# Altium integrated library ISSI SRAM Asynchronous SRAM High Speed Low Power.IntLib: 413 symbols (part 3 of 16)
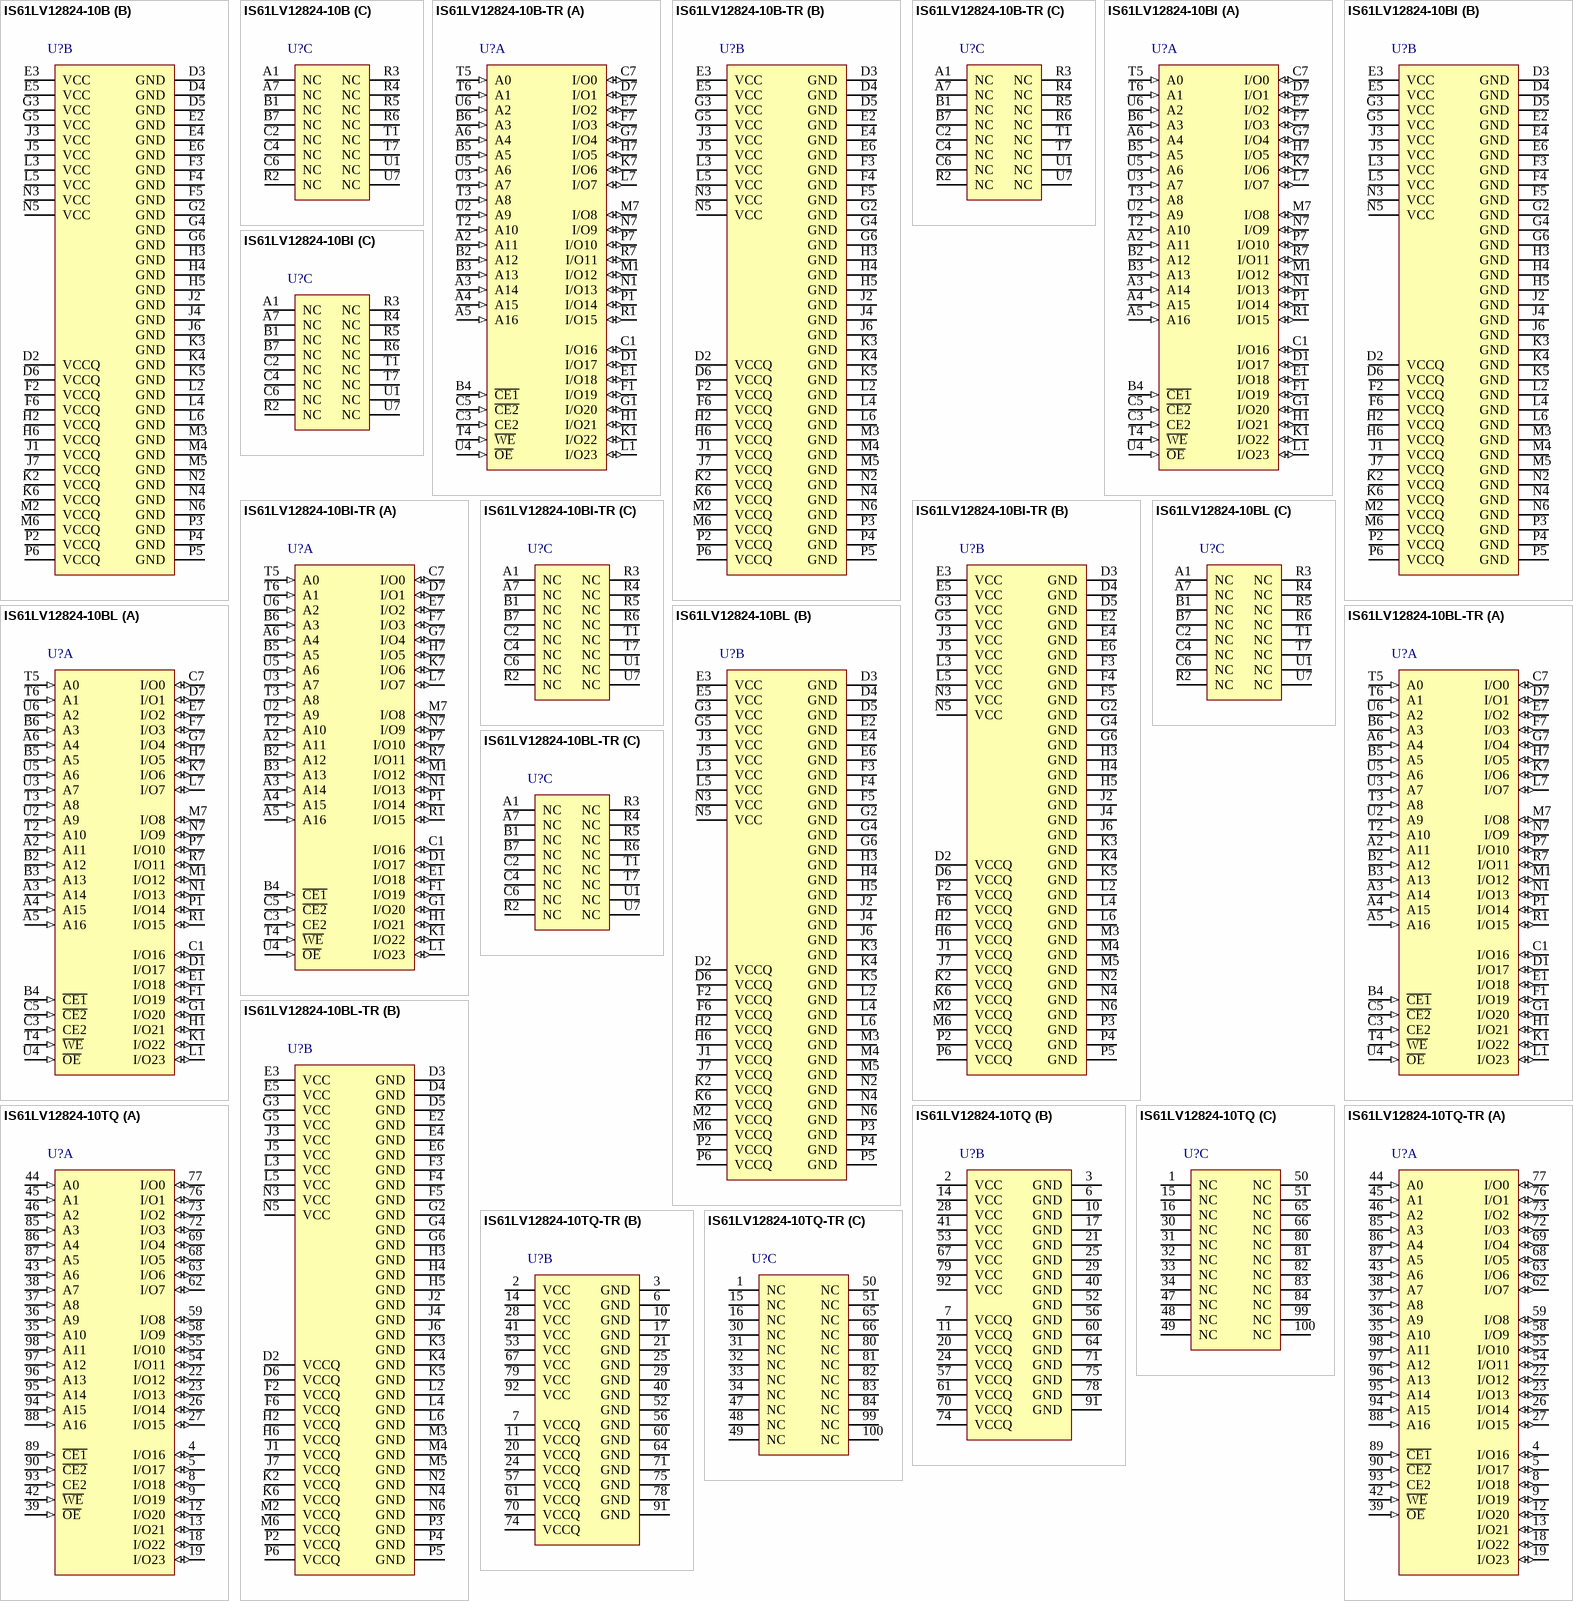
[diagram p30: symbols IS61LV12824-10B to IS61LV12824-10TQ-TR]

## IS61LV12824-10TQ-TR
designator U?
3 M High Speed CMOS SRAM with 3.3 V Supply, 128 K x 24, 0 to 70 degC, 100-Pin QFP (TQFP-100); Manufacturer: Integrated Silicon Solution Inc (ISSI); PartNumber: IS61LV12824-10TQ-TR; Density: 3M; Packing: Tape & Reel; Speed (ns): 10
footprint ISSI-TQFP-100-20000X14000DE_N (QFP, 100-Leads, Body 20x14mm, Pitch 0.65mm, IPC Medium Density)
part A pins: 4 I/O16 (io) "Data Input/Output", 5 I/O17 (io) "Data Input/Output", 8 I/O18 (io) "Data Input/Output", 9 I/O19 (io) "Data Input/Output", 12 I/O20 (io) "Data Input/Output", 13 I/O21 (io) "Data Input/Output", 18 I/O22 (io) "Data Input/Output", 19 I/O23 (io) "Data Input/Output", 22 I/O12 (io) "Data Input/Output", 23 I/O13 (io) "Data Input/Output", 26 I/O14 (io) "Data Input/Output", 27 I/O15 (io) "Data Input/Output", 35 A10 (in) "Address Input", 36 A9 (in) "Address Input", 37 A8 (in) "Address Input", 38 A7 (in) "Address Input", 39 ~{OE} (in) "Output Enable Input", 42 ~{WE} (in) "Write Enable Input", 43 A6 (in) "Address Input", 44 A0 (in) "Address Input", 45 A1 (in) "Address Input", 46 A2 (in) "Address Input", 54 I/O11 (io) "Data Input/Output", 55 I/O10 (io) "Data Input/Output", 58 I/O9 (io) "Data Input/Output", 59 I/O8 (io) "Data Input/Output", 62 I/O7 (io) "Data Input/Output", 63 I/O6 (io) "Data Input/Output", 68 I/O5 (io) "Data Input/Output", 69 I/O4 (io) "Data Input/Output", 72 I/O3 (io) "Data Input/Output", 73 I/O2 (io) "Data Input/Output", 76 I/O1 (io) "Data Input/Output", 77 I/O0 (io) "Data Input/Output", 85 A3 (in) "Address Input", 86 A4 (in) "Address Input", 87 A5 (in) "Address Input", 88 A16 (in) "Address Input", 89 ~{CE1} (in) "Chip Enable Input LOW", 90 ~{CE2} (in) "Chip Enable Input LOW", 93 CE2 (in) "Chip Enable Input HIGH", 94 A15 (in) "Address Input", 95 A14 (in) "Address Input", 96 A13 (in) "Address Input", 97 A12 (in) "Address Input", 98 A11 (in) "Address Input"
part B pins: 2 VCC (power) "Power", 3 GND (power) "Ground", 6 GND (power) "Ground", 7 VCCQ (power) "I/O Power", 10 GND (power) "Ground", 11 VCCQ (power) "I/O Power", 14 VCC (power) "Power", 17 GND (power) "Ground", 20 VCCQ (power) "I/O Power", 21 GND (power) "Ground", 24 VCCQ (power) "I/O Power", 25 GND (power) "Ground", 28 VCC (power) "Power", 29 GND (power) "Ground", 40 GND (power) "Ground", 41 VCC (power) "Power", 52 GND (power) "Ground", 53 VCC (power) "Power", 56 GND (power) "Ground", 57 VCCQ (power) "I/O Power", 60 GND (power) "Ground", 61 VCCQ (power) "I/O Power", 64 GND (power) "Ground", 67 VCC (power) "Power", 70 VCCQ (power) "I/O Power", 71 GND (power) "Ground", 74 VCCQ (power) "I/O Power", 75 GND (power) "Ground", 78 GND (power) "Ground", 79 VCC (power) "Power", 91 GND (power) "Ground", 92 VCC (power) "Power"
part C pins: 1 NC "No Connection", 15 NC "No Connection", 16 NC "No Connection", 30 NC "No Connection", 31 NC "No Connection", 32 NC "No Connection", 33 NC "No Connection", 34 NC "No Connection", 47 NC "No Connection", 48 NC "No Connection", 49 NC "No Connection", 50 NC "No Connection", 51 NC "No Connection", 65 NC "No Connection", 66 NC "No Connection", 80 NC "No Connection", 81 NC "No Connection", 82 NC "No Connection", 83 NC "No Connection", 84 NC "No Connection", 99 NC "No Connection", 100 NC "No Connection"

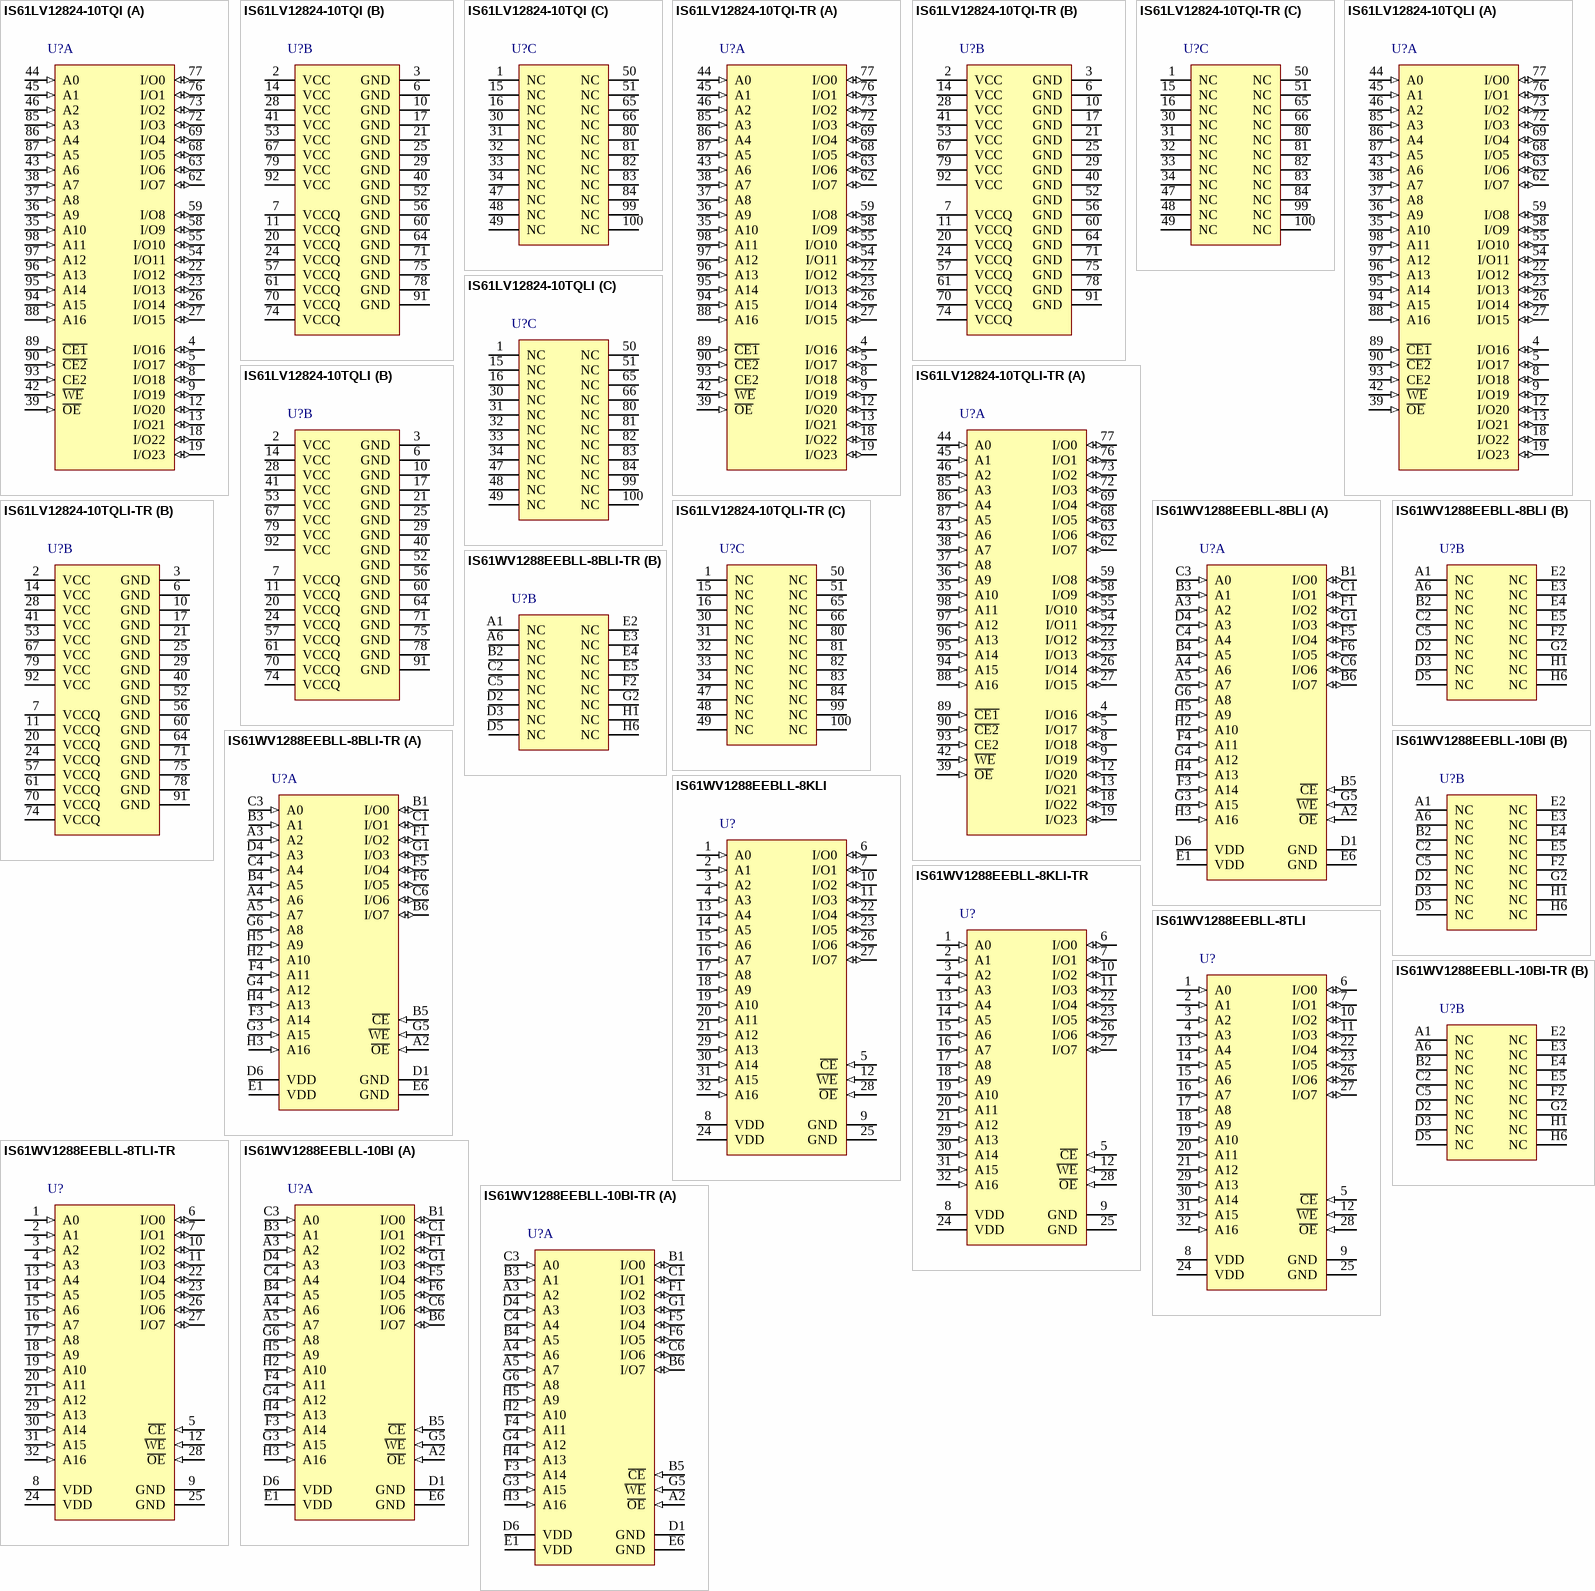
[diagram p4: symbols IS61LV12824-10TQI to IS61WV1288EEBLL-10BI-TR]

## IS61LV12824-10TQI
designator U?
3 M High Speed CMOS SRAM with 3.3 V Supply, 128 K x 24, -40 to 85 degC, 100-Pin QFP (TQFP-100); Manufacturer: Integrated Silicon Solution Inc (ISSI); PartNumber: IS61LV12824-10TQI; Density: 3M; Packing: Tray / Tube; Speed (ns): 10
footprint ISSI-TQFP-100-20000X14000DE_N (QFP, 100-Leads, Body 20x14mm, Pitch 0.65mm, IPC Medium Density)
part A pins: 4 I/O16 (io) "Data Input/Output", 5 I/O17 (io) "Data Input/Output", 8 I/O18 (io) "Data Input/Output", 9 I/O19 (io) "Data Input/Output", 12 I/O20 (io) "Data Input/Output", 13 I/O21 (io) "Data Input/Output", 18 I/O22 (io) "Data Input/Output", 19 I/O23 (io) "Data Input/Output", 22 I/O12 (io) "Data Input/Output", 23 I/O13 (io) "Data Input/Output", 26 I/O14 (io) "Data Input/Output", 27 I/O15 (io) "Data Input/Output", 35 A10 (in) "Address Input", 36 A9 (in) "Address Input", 37 A8 (in) "Address Input", 38 A7 (in) "Address Input", 39 ~{OE} (in) "Output Enable Input", 42 ~{WE} (in) "Write Enable Input", 43 A6 (in) "Address Input", 44 A0 (in) "Address Input", 45 A1 (in) "Address Input", 46 A2 (in) "Address Input", 54 I/O11 (io) "Data Input/Output", 55 I/O10 (io) "Data Input/Output", 58 I/O9 (io) "Data Input/Output", 59 I/O8 (io) "Data Input/Output", 62 I/O7 (io) "Data Input/Output", 63 I/O6 (io) "Data Input/Output", 68 I/O5 (io) "Data Input/Output", 69 I/O4 (io) "Data Input/Output", 72 I/O3 (io) "Data Input/Output", 73 I/O2 (io) "Data Input/Output", 76 I/O1 (io) "Data Input/Output", 77 I/O0 (io) "Data Input/Output", 85 A3 (in) "Address Input", 86 A4 (in) "Address Input", 87 A5 (in) "Address Input", 88 A16 (in) "Address Input", 89 ~{CE1} (in) "Chip Enable Input LOW", 90 ~{CE2} (in) "Chip Enable Input LOW", 93 CE2 (in) "Chip Enable Input HIGH", 94 A15 (in) "Address Input", 95 A14 (in) "Address Input", 96 A13 (in) "Address Input", 97 A12 (in) "Address Input", 98 A11 (in) "Address Input"
part B pins: 2 VCC (power) "Power", 3 GND (power) "Ground", 6 GND (power) "Ground", 7 VCCQ (power) "I/O Power", 10 GND (power) "Ground", 11 VCCQ (power) "I/O Power", 14 VCC (power) "Power", 17 GND (power) "Ground", 20 VCCQ (power) "I/O Power", 21 GND (power) "Ground", 24 VCCQ (power) "I/O Power", 25 GND (power) "Ground", 28 VCC (power) "Power", 29 GND (power) "Ground", 40 GND (power) "Ground", 41 VCC (power) "Power", 52 GND (power) "Ground", 53 VCC (power) "Power", 56 GND (power) "Ground", 57 VCCQ (power) "I/O Power", 60 GND (power) "Ground", 61 VCCQ (power) "I/O Power", 64 GND (power) "Ground", 67 VCC (power) "Power", 70 VCCQ (power) "I/O Power", 71 GND (power) "Ground", 74 VCCQ (power) "I/O Power", 75 GND (power) "Ground", 78 GND (power) "Ground", 79 VCC (power) "Power", 91 GND (power) "Ground", 92 VCC (power) "Power"
part C pins: 1 NC "No Connection", 15 NC "No Connection", 16 NC "No Connection", 30 NC "No Connection", 31 NC "No Connection", 32 NC "No Connection", 33 NC "No Connection", 34 NC "No Connection", 47 NC "No Connection", 48 NC "No Connection", 49 NC "No Connection", 50 NC "No Connection", 51 NC "No Connection", 65 NC "No Connection", 66 NC "No Connection", 80 NC "No Connection", 81 NC "No Connection", 82 NC "No Connection", 83 NC "No Connection", 84 NC "No Connection", 99 NC "No Connection", 100 NC "No Connection"

## IS61LV12824-10TQI-TR
designator U?
3 M High Speed CMOS SRAM with 3.3 V Supply, 128 K x 24, -40 to 85 degC, 100-Pin QFP (TQFP-100); Manufacturer: Integrated Silicon Solution Inc (ISSI); PartNumber: IS61LV12824-10TQI-TR; Density: 3M; Packing: Tape & Reel; Speed (ns): 10
footprint ISSI-TQFP-100-20000X14000DE_N (QFP, 100-Leads, Body 20x14mm, Pitch 0.65mm, IPC Medium Density)
part A pins: 4 I/O16 (io) "Data Input/Output", 5 I/O17 (io) "Data Input/Output", 8 I/O18 (io) "Data Input/Output", 9 I/O19 (io) "Data Input/Output", 12 I/O20 (io) "Data Input/Output", 13 I/O21 (io) "Data Input/Output", 18 I/O22 (io) "Data Input/Output", 19 I/O23 (io) "Data Input/Output", 22 I/O12 (io) "Data Input/Output", 23 I/O13 (io) "Data Input/Output", 26 I/O14 (io) "Data Input/Output", 27 I/O15 (io) "Data Input/Output", 35 A10 (in) "Address Input", 36 A9 (in) "Address Input", 37 A8 (in) "Address Input", 38 A7 (in) "Address Input", 39 ~{OE} (in) "Output Enable Input", 42 ~{WE} (in) "Write Enable Input", 43 A6 (in) "Address Input", 44 A0 (in) "Address Input", 45 A1 (in) "Address Input", 46 A2 (in) "Address Input", 54 I/O11 (io) "Data Input/Output", 55 I/O10 (io) "Data Input/Output", 58 I/O9 (io) "Data Input/Output", 59 I/O8 (io) "Data Input/Output", 62 I/O7 (io) "Data Input/Output", 63 I/O6 (io) "Data Input/Output", 68 I/O5 (io) "Data Input/Output", 69 I/O4 (io) "Data Input/Output", 72 I/O3 (io) "Data Input/Output", 73 I/O2 (io) "Data Input/Output", 76 I/O1 (io) "Data Input/Output", 77 I/O0 (io) "Data Input/Output", 85 A3 (in) "Address Input", 86 A4 (in) "Address Input", 87 A5 (in) "Address Input", 88 A16 (in) "Address Input", 89 ~{CE1} (in) "Chip Enable Input LOW", 90 ~{CE2} (in) "Chip Enable Input LOW", 93 CE2 (in) "Chip Enable Input HIGH", 94 A15 (in) "Address Input", 95 A14 (in) "Address Input", 96 A13 (in) "Address Input", 97 A12 (in) "Address Input", 98 A11 (in) "Address Input"
part B pins: 2 VCC (power) "Power", 3 GND (power) "Ground", 6 GND (power) "Ground", 7 VCCQ (power) "I/O Power", 10 GND (power) "Ground", 11 VCCQ (power) "I/O Power", 14 VCC (power) "Power", 17 GND (power) "Ground", 20 VCCQ (power) "I/O Power", 21 GND (power) "Ground", 24 VCCQ (power) "I/O Power", 25 GND (power) "Ground", 28 VCC (power) "Power", 29 GND (power) "Ground", 40 GND (power) "Ground", 41 VCC (power) "Power", 52 GND (power) "Ground", 53 VCC (power) "Power", 56 GND (power) "Ground", 57 VCCQ (power) "I/O Power", 60 GND (power) "Ground", 61 VCCQ (power) "I/O Power", 64 GND (power) "Ground", 67 VCC (power) "Power", 70 VCCQ (power) "I/O Power", 71 GND (power) "Ground", 74 VCCQ (power) "I/O Power", 75 GND (power) "Ground", 78 GND (power) "Ground", 79 VCC (power) "Power", 91 GND (power) "Ground", 92 VCC (power) "Power"
part C pins: 1 NC "No Connection", 15 NC "No Connection", 16 NC "No Connection", 30 NC "No Connection", 31 NC "No Connection", 32 NC "No Connection", 33 NC "No Connection", 34 NC "No Connection", 47 NC "No Connection", 48 NC "No Connection", 49 NC "No Connection", 50 NC "No Connection", 51 NC "No Connection", 65 NC "No Connection", 66 NC "No Connection", 80 NC "No Connection", 81 NC "No Connection", 82 NC "No Connection", 83 NC "No Connection", 84 NC "No Connection", 99 NC "No Connection", 100 NC "No Connection"

## IS61LV12824-10TQLI
designator U?
3 M High Speed CMOS SRAM with 3.3 V Supply, 128 K x 24, -40 to 85 degC, 100-Pin QFP (TQFP-100), Pb-Free; Manufacturer: Integrated Silicon Solution Inc (ISSI); PartNumber: IS61LV12824-10TQLI; Density: 3M; Packing: Tray / Tube; Speed (ns): 10
footprint ISSI-TQFP-100-20000X14000DE_N (QFP, 100-Leads, Body 20x14mm, Pitch 0.65mm, IPC Medium Density)
part A pins: 4 I/O16 (io) "Data Input/Output", 5 I/O17 (io) "Data Input/Output", 8 I/O18 (io) "Data Input/Output", 9 I/O19 (io) "Data Input/Output", 12 I/O20 (io) "Data Input/Output", 13 I/O21 (io) "Data Input/Output", 18 I/O22 (io) "Data Input/Output", 19 I/O23 (io) "Data Input/Output", 22 I/O12 (io) "Data Input/Output", 23 I/O13 (io) "Data Input/Output", 26 I/O14 (io) "Data Input/Output", 27 I/O15 (io) "Data Input/Output", 35 A10 (in) "Address Input", 36 A9 (in) "Address Input", 37 A8 (in) "Address Input", 38 A7 (in) "Address Input", 39 ~{OE} (in) "Output Enable Input", 42 ~{WE} (in) "Write Enable Input", 43 A6 (in) "Address Input", 44 A0 (in) "Address Input", 45 A1 (in) "Address Input", 46 A2 (in) "Address Input", 54 I/O11 (io) "Data Input/Output", 55 I/O10 (io) "Data Input/Output", 58 I/O9 (io) "Data Input/Output", 59 I/O8 (io) "Data Input/Output", 62 I/O7 (io) "Data Input/Output", 63 I/O6 (io) "Data Input/Output", 68 I/O5 (io) "Data Input/Output", 69 I/O4 (io) "Data Input/Output", 72 I/O3 (io) "Data Input/Output", 73 I/O2 (io) "Data Input/Output", 76 I/O1 (io) "Data Input/Output", 77 I/O0 (io) "Data Input/Output", 85 A3 (in) "Address Input", 86 A4 (in) "Address Input", 87 A5 (in) "Address Input", 88 A16 (in) "Address Input", 89 ~{CE1} (in) "Chip Enable Input LOW", 90 ~{CE2} (in) "Chip Enable Input LOW", 93 CE2 (in) "Chip Enable Input HIGH", 94 A15 (in) "Address Input", 95 A14 (in) "Address Input", 96 A13 (in) "Address Input", 97 A12 (in) "Address Input", 98 A11 (in) "Address Input"
part B pins: 2 VCC (power) "Power", 3 GND (power) "Ground", 6 GND (power) "Ground", 7 VCCQ (power) "I/O Power", 10 GND (power) "Ground", 11 VCCQ (power) "I/O Power", 14 VCC (power) "Power", 17 GND (power) "Ground", 20 VCCQ (power) "I/O Power", 21 GND (power) "Ground", 24 VCCQ (power) "I/O Power", 25 GND (power) "Ground", 28 VCC (power) "Power", 29 GND (power) "Ground", 40 GND (power) "Ground", 41 VCC (power) "Power", 52 GND (power) "Ground", 53 VCC (power) "Power", 56 GND (power) "Ground", 57 VCCQ (power) "I/O Power", 60 GND (power) "Ground", 61 VCCQ (power) "I/O Power", 64 GND (power) "Ground", 67 VCC (power) "Power", 70 VCCQ (power) "I/O Power", 71 GND (power) "Ground", 74 VCCQ (power) "I/O Power", 75 GND (power) "Ground", 78 GND (power) "Ground", 79 VCC (power) "Power", 91 GND (power) "Ground", 92 VCC (power) "Power"
part C pins: 1 NC "No Connection", 15 NC "No Connection", 16 NC "No Connection", 30 NC "No Connection", 31 NC "No Connection", 32 NC "No Connection", 33 NC "No Connection", 34 NC "No Connection", 47 NC "No Connection", 48 NC "No Connection", 49 NC "No Connection", 50 NC "No Connection", 51 NC "No Connection", 65 NC "No Connection", 66 NC "No Connection", 80 NC "No Connection", 81 NC "No Connection", 82 NC "No Connection", 83 NC "No Connection", 84 NC "No Connection", 99 NC "No Connection", 100 NC "No Connection"

## IS61LV12824-10TQLI-TR
designator U?
3 M High Speed CMOS SRAM with 3.3 V Supply, 128 K x 24, -40 to 85 degC, 100-Pin QFP (TQFP-100), Pb-Free; Manufacturer: Integrated Silicon Solution Inc (ISSI); PartNumber: IS61LV12824-10TQLI-TR; Density: 3M; Packing: Tape & Reel; Speed (ns): 10
footprint ISSI-TQFP-100-20000X14000DE_N (QFP, 100-Leads, Body 20x14mm, Pitch 0.65mm, IPC Medium Density)
part A pins: 4 I/O16 (io) "Data Input/Output", 5 I/O17 (io) "Data Input/Output", 8 I/O18 (io) "Data Input/Output", 9 I/O19 (io) "Data Input/Output", 12 I/O20 (io) "Data Input/Output", 13 I/O21 (io) "Data Input/Output", 18 I/O22 (io) "Data Input/Output", 19 I/O23 (io) "Data Input/Output", 22 I/O12 (io) "Data Input/Output", 23 I/O13 (io) "Data Input/Output", 26 I/O14 (io) "Data Input/Output", 27 I/O15 (io) "Data Input/Output", 35 A10 (in) "Address Input", 36 A9 (in) "Address Input", 37 A8 (in) "Address Input", 38 A7 (in) "Address Input", 39 ~{OE} (in) "Output Enable Input", 42 ~{WE} (in) "Write Enable Input", 43 A6 (in) "Address Input", 44 A0 (in) "Address Input", 45 A1 (in) "Address Input", 46 A2 (in) "Address Input", 54 I/O11 (io) "Data Input/Output", 55 I/O10 (io) "Data Input/Output", 58 I/O9 (io) "Data Input/Output", 59 I/O8 (io) "Data Input/Output", 62 I/O7 (io) "Data Input/Output", 63 I/O6 (io) "Data Input/Output", 68 I/O5 (io) "Data Input/Output", 69 I/O4 (io) "Data Input/Output", 72 I/O3 (io) "Data Input/Output", 73 I/O2 (io) "Data Input/Output", 76 I/O1 (io) "Data Input/Output", 77 I/O0 (io) "Data Input/Output", 85 A3 (in) "Address Input", 86 A4 (in) "Address Input", 87 A5 (in) "Address Input", 88 A16 (in) "Address Input", 89 ~{CE1} (in) "Chip Enable Input LOW", 90 ~{CE2} (in) "Chip Enable Input LOW", 93 CE2 (in) "Chip Enable Input HIGH", 94 A15 (in) "Address Input", 95 A14 (in) "Address Input", 96 A13 (in) "Address Input", 97 A12 (in) "Address Input", 98 A11 (in) "Address Input"
part B pins: 2 VCC (power) "Power", 3 GND (power) "Ground", 6 GND (power) "Ground", 7 VCCQ (power) "I/O Power", 10 GND (power) "Ground", 11 VCCQ (power) "I/O Power", 14 VCC (power) "Power", 17 GND (power) "Ground", 20 VCCQ (power) "I/O Power", 21 GND (power) "Ground", 24 VCCQ (power) "I/O Power", 25 GND (power) "Ground", 28 VCC (power) "Power", 29 GND (power) "Ground", 40 GND (power) "Ground", 41 VCC (power) "Power", 52 GND (power) "Ground", 53 VCC (power) "Power", 56 GND (power) "Ground", 57 VCCQ (power) "I/O Power", 60 GND (power) "Ground", 61 VCCQ (power) "I/O Power", 64 GND (power) "Ground", 67 VCC (power) "Power", 70 VCCQ (power) "I/O Power", 71 GND (power) "Ground", 74 VCCQ (power) "I/O Power", 75 GND (power) "Ground", 78 GND (power) "Ground", 79 VCC (power) "Power", 91 GND (power) "Ground", 92 VCC (power) "Power"
part C pins: 1 NC "No Connection", 15 NC "No Connection", 16 NC "No Connection", 30 NC "No Connection", 31 NC "No Connection", 32 NC "No Connection", 33 NC "No Connection", 34 NC "No Connection", 47 NC "No Connection", 48 NC "No Connection", 49 NC "No Connection", 50 NC "No Connection", 51 NC "No Connection", 65 NC "No Connection", 66 NC "No Connection", 80 NC "No Connection", 81 NC "No Connection", 82 NC "No Connection", 83 NC "No Connection", 84 NC "No Connection", 99 NC "No Connection", 100 NC "No Connection"

## IS61WV1288EEBLL-8BLI
designator U?
1 M High Speed Asynchronous CMOS SRAM with ECC, 128 K x 8, -40 to 85 degC, 48-Pin BGA (TF-BGA-48), Pb-Free; Manufacturer: Integrated Silicon Solution Inc (ISSI); PartNumber: IS61WV1288EEBLL-8BLI; Density: 1M; Organization: 128K x 8; Packing: Tray / Tube; Speed (ns): 8
footprint ISSI-TF-BGA-48-6000X8000DE (BGA, 48-Balls, Body 8x6mm, Pitch 0.75mm)
part A pins: A2 ~{OE} (in) "Output Enable Input", A3 A2 (in) "Address Input", A4 A6 (in) "Address Input", A5 A7 (in) "Address Input", B1 I/O0 (io) "Bidirectional Port", B3 A1 (in) "Address Input", B4 A5 (in) "Address Input", B5 ~{CE} (in) "Chip Enable Input", B6 I/O7 (io) "Bidirectional Port", C1 I/O1 (io) "Bidirectional Port", C3 A0 (in) "Address Input", C4 A4 (in) "Address Input", C6 I/O6 (io) "Bidirectional Port", D1 GND (power) "Ground", D4 A3 (in) "Address Input", D6 VDD (power) "Power", E1 VDD (power) "Power", E6 GND (power) "Ground", F1 I/O2 (io) "Bidirectional Port", F3 A14 (in) "Address Input", F4 A11 (in) "Address Input", F5 I/O4 (io) "Bidirectional Port", F6 I/O5 (io) "Bidirectional Port", G1 I/O3 (io) "Bidirectional Port", G3 A15 (in) "Address Input", G4 A12 (in) "Address Input", G5 ~{WE} (in) "Write Enable Input", G6 A8 (in) "Address Input", H2 A10 (in) "Address Input", H3 A16 (in) "Address Input", H4 A13 (in) "Address Input", H5 A9 (in) "Address Input"
part B pins: A1 NC "No Connection", A6 NC "No Connection", B2 NC "No Connection", C2 NC "No Connection", C5 NC "No Connection", D2 NC "No Connection", D3 NC "No Connection", D5 NC "No Connection", E2 NC "No Connection", E3 NC "No Connection", E4 NC "No Connection", E5 NC "No Connection", F2 NC "No Connection", G2 NC "No Connection", H1 NC "No Connection", H6 NC "No Connection"

## IS61WV1288EEBLL-8BLI-TR
designator U?
1 M High Speed Asynchronous CMOS SRAM with ECC, 128 K x 8, -40 to 85 degC, 48-Pin BGA (TF-BGA-48), Pb-Free; Manufacturer: Integrated Silicon Solution Inc (ISSI); PartNumber: IS61WV1288EEBLL-8BLI-TR; Density: 1M; Organization: 128K x 8; Packing: Tape & Reel; Speed (ns): 8
footprint ISSI-TF-BGA-48-6000X8000DE (BGA, 48-Balls, Body 8x6mm, Pitch 0.75mm)
part A pins: A2 ~{OE} (in) "Output Enable Input", A3 A2 (in) "Address Input", A4 A6 (in) "Address Input", A5 A7 (in) "Address Input", B1 I/O0 (io) "Bidirectional Port", B3 A1 (in) "Address Input", B4 A5 (in) "Address Input", B5 ~{CE} (in) "Chip Enable Input", B6 I/O7 (io) "Bidirectional Port", C1 I/O1 (io) "Bidirectional Port", C3 A0 (in) "Address Input", C4 A4 (in) "Address Input", C6 I/O6 (io) "Bidirectional Port", D1 GND (power) "Ground", D4 A3 (in) "Address Input", D6 VDD (power) "Power", E1 VDD (power) "Power", E6 GND (power) "Ground", F1 I/O2 (io) "Bidirectional Port", F3 A14 (in) "Address Input", F4 A11 (in) "Address Input", F5 I/O4 (io) "Bidirectional Port", F6 I/O5 (io) "Bidirectional Port", G1 I/O3 (io) "Bidirectional Port", G3 A15 (in) "Address Input", G4 A12 (in) "Address Input", G5 ~{WE} (in) "Write Enable Input", G6 A8 (in) "Address Input", H2 A10 (in) "Address Input", H3 A16 (in) "Address Input", H4 A13 (in) "Address Input", H5 A9 (in) "Address Input"
part B pins: A1 NC "No Connection", A6 NC "No Connection", B2 NC "No Connection", C2 NC "No Connection", C5 NC "No Connection", D2 NC "No Connection", D3 NC "No Connection", D5 NC "No Connection", E2 NC "No Connection", E3 NC "No Connection", E4 NC "No Connection", E5 NC "No Connection", F2 NC "No Connection", G2 NC "No Connection", H1 NC "No Connection", H6 NC "No Connection"

## IS61WV1288EEBLL-8KLI
designator U?
1 M High Speed Asynchronous CMOS SRAM with ECC, 128 K x 8, -40 to 85 degC, 32-Pin SOJ (SOJ-32_B), Pb-Free; Manufacturer: Integrated Silicon Solution Inc (ISSI); PartNumber: IS61WV1288EEBLL-8KLI; Density: 1M; Organization: 128K x 8; Packing: Tray / Tube; Speed (ns): 8
footprint ISSI-SOJ-32_B_N (SOJ, 32-Leads, Body 21.08x10.29mm, Pitch 1.27mm, IPC Medium Density)
pins: 1 A0 (in) "Address Input", 2 A1 (in) "Address Input", 3 A2 (in) "Address Input", 4 A3 (in) "Address Input", 5 ~{CE} (in) "Chip Enable Input", 6 I/O0 (io) "Bidirectional Port", 7 I/O1 (io) "Bidirectional Port", 8 VDD (power) "Power", 9 GND (power) "Ground", 10 I/O2 (io) "Bidirectional Port", 11 I/O3 (io) "Bidirectional Port", 12 ~{WE} (in) "Write Enable Input", 13 A4 (in) "Address Input", 14 A5 (in) "Address Input", 15 A6 (in) "Address Input", 16 A7 (in) "Address Input", 17 A8 (in) "Address Input", 18 A9 (in) "Address Input", 19 A10 (in) "Address Input", 20 A11 (in) "Address Input", 21 A12 (in) "Address Input", 22 I/O4 (io) "Bidirectional Port", 23 I/O5 (io) "Bidirectional Port", 24 VDD (power) "Power", 25 GND (power) "Ground", 26 I/O6 (io) "Bidirectional Port", 27 I/O7 (io) "Bidirectional Port", 28 ~{OE} (in) "Output Enable Input", 29 A13 (in) "Address Input", 30 A14 (in) "Address Input", 31 A15 (in) "Address Input", 32 A16 (in) "Address Input"

## IS61WV1288EEBLL-8KLI-TR
designator U?
1 M High Speed Asynchronous CMOS SRAM with ECC, 128 K x 8, -40 to 85 degC, 32-Pin SOJ (SOJ-32_B), Pb-Free; Manufacturer: Integrated Silicon Solution Inc (ISSI); PartNumber: IS61WV1288EEBLL-8KLI-TR; Density: 1M; Organization: 128K x 8; Packing: Tape & Reel; Speed (ns): 8
footprint ISSI-SOJ-32_B_N (SOJ, 32-Leads, Body 21.08x10.29mm, Pitch 1.27mm, IPC Medium Density)
pins: 1 A0 (in) "Address Input", 2 A1 (in) "Address Input", 3 A2 (in) "Address Input", 4 A3 (in) "Address Input", 5 ~{CE} (in) "Chip Enable Input", 6 I/O0 (io) "Bidirectional Port", 7 I/O1 (io) "Bidirectional Port", 8 VDD (power) "Power", 9 GND (power) "Ground", 10 I/O2 (io) "Bidirectional Port", 11 I/O3 (io) "Bidirectional Port", 12 ~{WE} (in) "Write Enable Input", 13 A4 (in) "Address Input", 14 A5 (in) "Address Input", 15 A6 (in) "Address Input", 16 A7 (in) "Address Input", 17 A8 (in) "Address Input", 18 A9 (in) "Address Input", 19 A10 (in) "Address Input", 20 A11 (in) "Address Input", 21 A12 (in) "Address Input", 22 I/O4 (io) "Bidirectional Port", 23 I/O5 (io) "Bidirectional Port", 24 VDD (power) "Power", 25 GND (power) "Ground", 26 I/O6 (io) "Bidirectional Port", 27 I/O7 (io) "Bidirectional Port", 28 ~{OE} (in) "Output Enable Input", 29 A13 (in) "Address Input", 30 A14 (in) "Address Input", 31 A15 (in) "Address Input", 32 A16 (in) "Address Input"

## IS61WV1288EEBLL-8TLI
designator U?
1 M High Speed Asynchronous CMOS SRAM with ECC, 128 K x 8, -40 to 85 degC, 32-Pin SOP (TSOP-2-32), Pb-Free; Manufacturer: Integrated Silicon Solution Inc (ISSI); PartNumber: IS61WV1288EEBLL-8TLI; Density: 1M; Organization: 128K x 8; Packing: Tray / Tube; Speed (ns): 8
footprint ISSI-TSOP-2-32_N (SOP, 32-Leads, Body 21.1x10.3mm, Pitch 1.27mm, IPC Medium Density)
pins: 1 A0 (in) "Address Input", 2 A1 (in) "Address Input", 3 A2 (in) "Address Input", 4 A3 (in) "Address Input", 5 ~{CE} (in) "Chip Enable Input", 6 I/O0 (io) "Bidirectional Port", 7 I/O1 (io) "Bidirectional Port", 8 VDD (power) "Power", 9 GND (power) "Ground", 10 I/O2 (io) "Bidirectional Port", 11 I/O3 (io) "Bidirectional Port", 12 ~{WE} (in) "Write Enable Input", 13 A4 (in) "Address Input", 14 A5 (in) "Address Input", 15 A6 (in) "Address Input", 16 A7 (in) "Address Input", 17 A8 (in) "Address Input", 18 A9 (in) "Address Input", 19 A10 (in) "Address Input", 20 A11 (in) "Address Input", 21 A12 (in) "Address Input", 22 I/O4 (io) "Bidirectional Port", 23 I/O5 (io) "Bidirectional Port", 24 VDD (power) "Power", 25 GND (power) "Ground", 26 I/O6 (io) "Bidirectional Port", 27 I/O7 (io) "Bidirectional Port", 28 ~{OE} (in) "Output Enable Input", 29 A13 (in) "Address Input", 30 A14 (in) "Address Input", 31 A15 (in) "Address Input", 32 A16 (in) "Address Input"

## IS61WV1288EEBLL-8TLI-TR
designator U?
1 M High Speed Asynchronous CMOS SRAM with ECC, 128 K x 8, -40 to 85 degC, 32-Pin SOP (TSOP-2-32), Pb-Free; Manufacturer: Integrated Silicon Solution Inc (ISSI); PartNumber: IS61WV1288EEBLL-8TLI-TR; Density: 1M; Organization: 128K x 8; Packing: Tape & Reel; Speed (ns): 8
footprint ISSI-TSOP-2-32_N (SOP, 32-Leads, Body 21.1x10.3mm, Pitch 1.27mm, IPC Medium Density)
pins: 1 A0 (in) "Address Input", 2 A1 (in) "Address Input", 3 A2 (in) "Address Input", 4 A3 (in) "Address Input", 5 ~{CE} (in) "Chip Enable Input", 6 I/O0 (io) "Bidirectional Port", 7 I/O1 (io) "Bidirectional Port", 8 VDD (power) "Power", 9 GND (power) "Ground", 10 I/O2 (io) "Bidirectional Port", 11 I/O3 (io) "Bidirectional Port", 12 ~{WE} (in) "Write Enable Input", 13 A4 (in) "Address Input", 14 A5 (in) "Address Input", 15 A6 (in) "Address Input", 16 A7 (in) "Address Input", 17 A8 (in) "Address Input", 18 A9 (in) "Address Input", 19 A10 (in) "Address Input", 20 A11 (in) "Address Input", 21 A12 (in) "Address Input", 22 I/O4 (io) "Bidirectional Port", 23 I/O5 (io) "Bidirectional Port", 24 VDD (power) "Power", 25 GND (power) "Ground", 26 I/O6 (io) "Bidirectional Port", 27 I/O7 (io) "Bidirectional Port", 28 ~{OE} (in) "Output Enable Input", 29 A13 (in) "Address Input", 30 A14 (in) "Address Input", 31 A15 (in) "Address Input", 32 A16 (in) "Address Input"

## IS61WV1288EEBLL-10BI
designator U?
1 M High Speed Asynchronous CMOS SRAM with ECC, 128 K x 8, -40 to 85 degC, 48-Pin BGA (TF-BGA-48); Manufacturer: Integrated Silicon Solution Inc (ISSI); PartNumber: IS61WV1288EEBLL-10BI; Density: 1M; Organization: 128K x 8; Packing: Tray / Tube; Speed (ns): 10
footprint ISSI-TF-BGA-48-6000X8000DE (BGA, 48-Balls, Body 8x6mm, Pitch 0.75mm)
part A pins: A2 ~{OE} (in) "Output Enable Input", A3 A2 (in) "Address Input", A4 A6 (in) "Address Input", A5 A7 (in) "Address Input", B1 I/O0 (io) "Bidirectional Port", B3 A1 (in) "Address Input", B4 A5 (in) "Address Input", B5 ~{CE} (in) "Chip Enable Input", B6 I/O7 (io) "Bidirectional Port", C1 I/O1 (io) "Bidirectional Port", C3 A0 (in) "Address Input", C4 A4 (in) "Address Input", C6 I/O6 (io) "Bidirectional Port", D1 GND (power) "Ground", D4 A3 (in) "Address Input", D6 VDD (power) "Power", E1 VDD (power) "Power", E6 GND (power) "Ground", F1 I/O2 (io) "Bidirectional Port", F3 A14 (in) "Address Input", F4 A11 (in) "Address Input", F5 I/O4 (io) "Bidirectional Port", F6 I/O5 (io) "Bidirectional Port", G1 I/O3 (io) "Bidirectional Port", G3 A15 (in) "Address Input", G4 A12 (in) "Address Input", G5 ~{WE} (in) "Write Enable Input", G6 A8 (in) "Address Input", H2 A10 (in) "Address Input", H3 A16 (in) "Address Input", H4 A13 (in) "Address Input", H5 A9 (in) "Address Input"
part B pins: A1 NC "No Connection", A6 NC "No Connection", B2 NC "No Connection", C2 NC "No Connection", C5 NC "No Connection", D2 NC "No Connection", D3 NC "No Connection", D5 NC "No Connection", E2 NC "No Connection", E3 NC "No Connection", E4 NC "No Connection", E5 NC "No Connection", F2 NC "No Connection", G2 NC "No Connection", H1 NC "No Connection", H6 NC "No Connection"

## IS61WV1288EEBLL-10BI-TR
designator U?
1 M High Speed Asynchronous CMOS SRAM with ECC, 128 K x 8, -40 to 85 degC, 48-Pin BGA (TF-BGA-48); Manufacturer: Integrated Silicon Solution Inc (ISSI); PartNumber: IS61WV1288EEBLL-10BI-TR; Density: 1M; Organization: 128K x 8; Packing: Tape & Reel; Speed (ns): 10
footprint ISSI-TF-BGA-48-6000X8000DE (BGA, 48-Balls, Body 8x6mm, Pitch 0.75mm)
part A pins: A2 ~{OE} (in) "Output Enable Input", A3 A2 (in) "Address Input", A4 A6 (in) "Address Input", A5 A7 (in) "Address Input", B1 I/O0 (io) "Bidirectional Port", B3 A1 (in) "Address Input", B4 A5 (in) "Address Input", B5 ~{CE} (in) "Chip Enable Input", B6 I/O7 (io) "Bidirectional Port", C1 I/O1 (io) "Bidirectional Port", C3 A0 (in) "Address Input", C4 A4 (in) "Address Input", C6 I/O6 (io) "Bidirectional Port", D1 GND (power) "Ground", D4 A3 (in) "Address Input", D6 VDD (power) "Power", E1 VDD (power) "Power", E6 GND (power) "Ground", F1 I/O2 (io) "Bidirectional Port", F3 A14 (in) "Address Input", F4 A11 (in) "Address Input", F5 I/O4 (io) "Bidirectional Port", F6 I/O5 (io) "Bidirectional Port", G1 I/O3 (io) "Bidirectional Port", G3 A15 (in) "Address Input", G4 A12 (in) "Address Input", G5 ~{WE} (in) "Write Enable Input", G6 A8 (in) "Address Input", H2 A10 (in) "Address Input", H3 A16 (in) "Address Input", H4 A13 (in) "Address Input", H5 A9 (in) "Address Input"
part B pins: A1 NC "No Connection", A6 NC "No Connection", B2 NC "No Connection", C2 NC "No Connection", C5 NC "No Connection", D2 NC "No Connection", D3 NC "No Connection", D5 NC "No Connection", E2 NC "No Connection", E3 NC "No Connection", E4 NC "No Connection", E5 NC "No Connection", F2 NC "No Connection", G2 NC "No Connection", H1 NC "No Connection", H6 NC "No Connection"

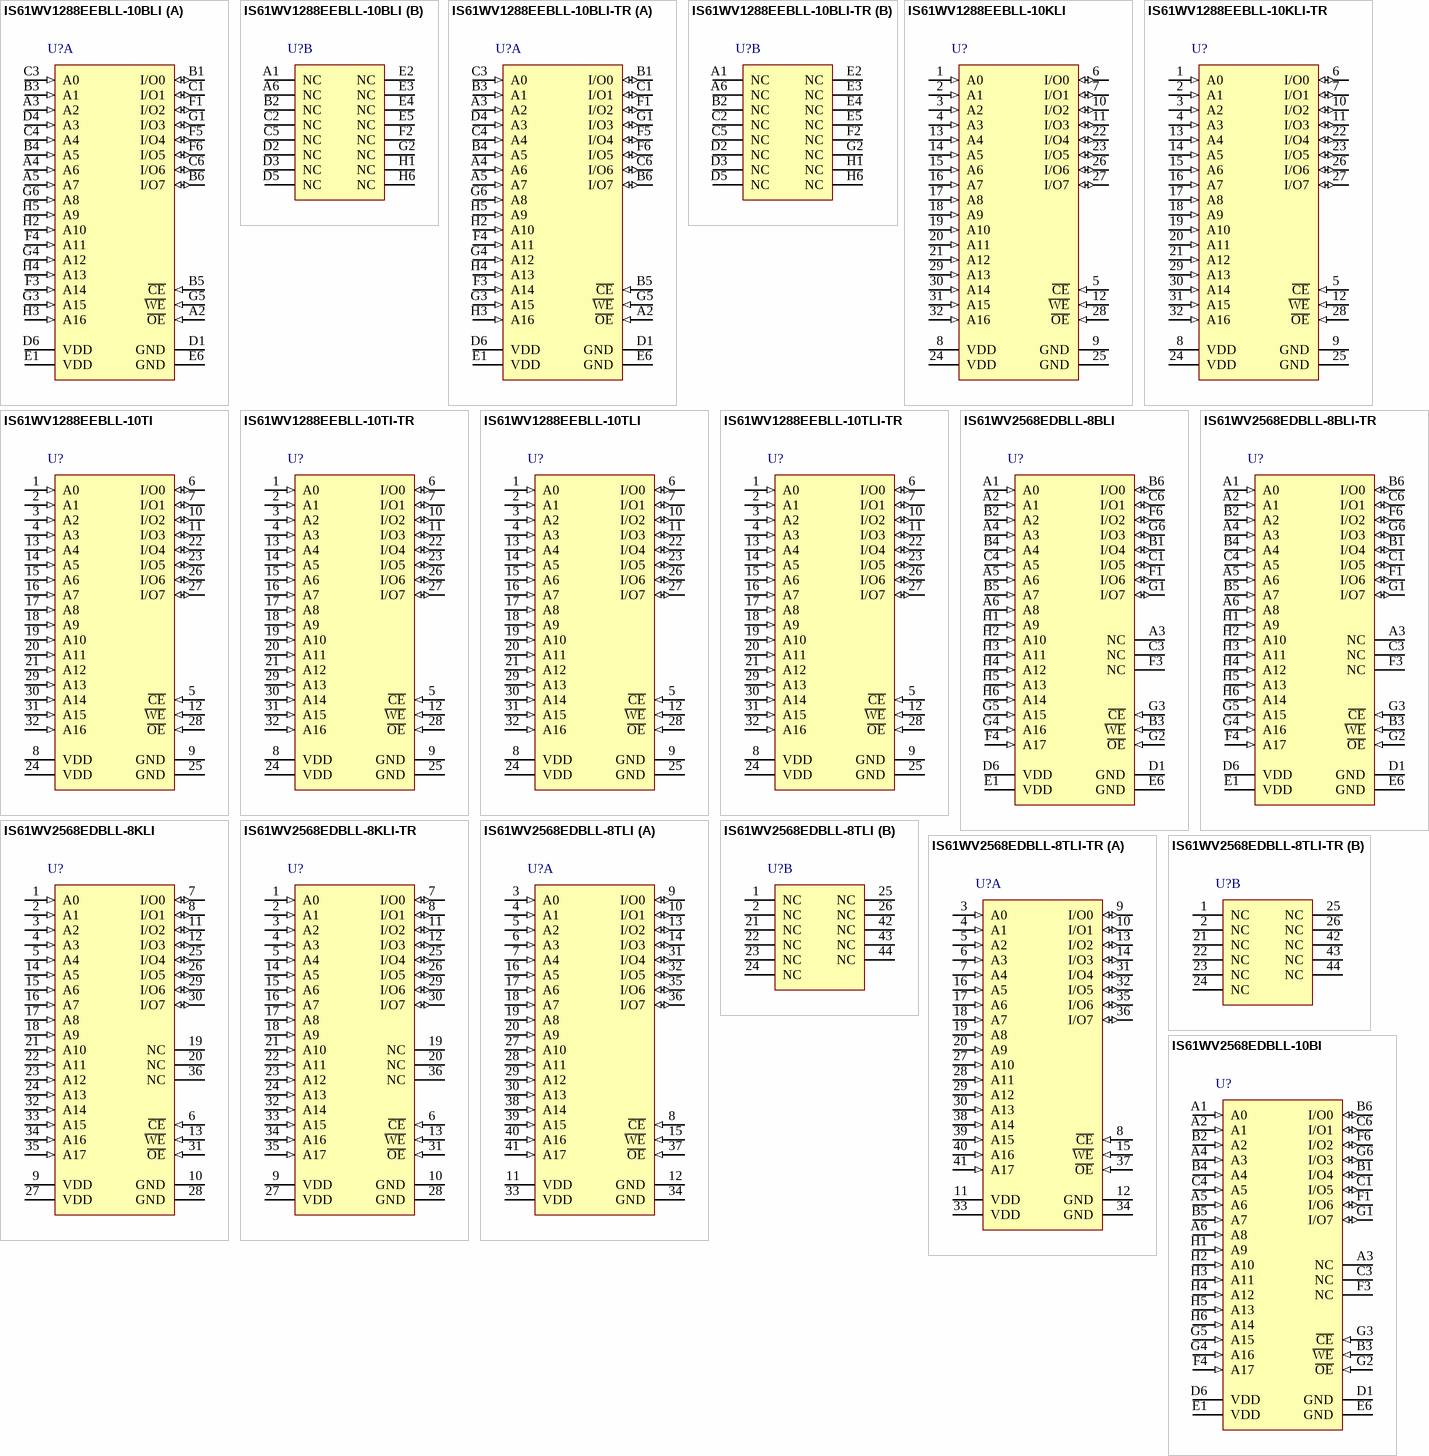
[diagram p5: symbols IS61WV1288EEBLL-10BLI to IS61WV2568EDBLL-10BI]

## IS61WV1288EEBLL-10BLI
designator U?
1 M High Speed Asynchronous CMOS SRAM with ECC, 128 K x 8, -40 to 85 degC, 48-Pin BGA (TF-BGA-48), Pb-Free; Manufacturer: Integrated Silicon Solution Inc (ISSI); PartNumber: IS61WV1288EEBLL-10BLI; Density: 1M; Organization: 128K x 8; Packing: Tray / Tube; Speed (ns): 10
footprint ISSI-TF-BGA-48-6000X8000DE (BGA, 48-Balls, Body 8x6mm, Pitch 0.75mm)
part A pins: A2 ~{OE} (in) "Output Enable Input", A3 A2 (in) "Address Input", A4 A6 (in) "Address Input", A5 A7 (in) "Address Input", B1 I/O0 (io) "Bidirectional Port", B3 A1 (in) "Address Input", B4 A5 (in) "Address Input", B5 ~{CE} (in) "Chip Enable Input", B6 I/O7 (io) "Bidirectional Port", C1 I/O1 (io) "Bidirectional Port", C3 A0 (in) "Address Input", C4 A4 (in) "Address Input", C6 I/O6 (io) "Bidirectional Port", D1 GND (power) "Ground", D4 A3 (in) "Address Input", D6 VDD (power) "Power", E1 VDD (power) "Power", E6 GND (power) "Ground", F1 I/O2 (io) "Bidirectional Port", F3 A14 (in) "Address Input", F4 A11 (in) "Address Input", F5 I/O4 (io) "Bidirectional Port", F6 I/O5 (io) "Bidirectional Port", G1 I/O3 (io) "Bidirectional Port", G3 A15 (in) "Address Input", G4 A12 (in) "Address Input", G5 ~{WE} (in) "Write Enable Input", G6 A8 (in) "Address Input", H2 A10 (in) "Address Input", H3 A16 (in) "Address Input", H4 A13 (in) "Address Input", H5 A9 (in) "Address Input"
part B pins: A1 NC "No Connection", A6 NC "No Connection", B2 NC "No Connection", C2 NC "No Connection", C5 NC "No Connection", D2 NC "No Connection", D3 NC "No Connection", D5 NC "No Connection", E2 NC "No Connection", E3 NC "No Connection", E4 NC "No Connection", E5 NC "No Connection", F2 NC "No Connection", G2 NC "No Connection", H1 NC "No Connection", H6 NC "No Connection"

## IS61WV1288EEBLL-10BLI-TR
designator U?
1 M High Speed Asynchronous CMOS SRAM with ECC, 128 K x 8, -40 to 85 degC, 48-Pin BGA (TF-BGA-48), Pb-Free; Manufacturer: Integrated Silicon Solution Inc (ISSI); PartNumber: IS61WV1288EEBLL-10BLI-TR; Density: 1M; Organization: 128K x 8; Packing: Tape & Reel; Speed (ns): 10
footprint ISSI-TF-BGA-48-6000X8000DE (BGA, 48-Balls, Body 8x6mm, Pitch 0.75mm)
part A pins: A2 ~{OE} (in) "Output Enable Input", A3 A2 (in) "Address Input", A4 A6 (in) "Address Input", A5 A7 (in) "Address Input", B1 I/O0 (io) "Bidirectional Port", B3 A1 (in) "Address Input", B4 A5 (in) "Address Input", B5 ~{CE} (in) "Chip Enable Input", B6 I/O7 (io) "Bidirectional Port", C1 I/O1 (io) "Bidirectional Port", C3 A0 (in) "Address Input", C4 A4 (in) "Address Input", C6 I/O6 (io) "Bidirectional Port", D1 GND (power) "Ground", D4 A3 (in) "Address Input", D6 VDD (power) "Power", E1 VDD (power) "Power", E6 GND (power) "Ground", F1 I/O2 (io) "Bidirectional Port", F3 A14 (in) "Address Input", F4 A11 (in) "Address Input", F5 I/O4 (io) "Bidirectional Port", F6 I/O5 (io) "Bidirectional Port", G1 I/O3 (io) "Bidirectional Port", G3 A15 (in) "Address Input", G4 A12 (in) "Address Input", G5 ~{WE} (in) "Write Enable Input", G6 A8 (in) "Address Input", H2 A10 (in) "Address Input", H3 A16 (in) "Address Input", H4 A13 (in) "Address Input", H5 A9 (in) "Address Input"
part B pins: A1 NC "No Connection", A6 NC "No Connection", B2 NC "No Connection", C2 NC "No Connection", C5 NC "No Connection", D2 NC "No Connection", D3 NC "No Connection", D5 NC "No Connection", E2 NC "No Connection", E3 NC "No Connection", E4 NC "No Connection", E5 NC "No Connection", F2 NC "No Connection", G2 NC "No Connection", H1 NC "No Connection", H6 NC "No Connection"

## IS61WV1288EEBLL-10KLI
designator U?
1 M High Speed Asynchronous CMOS SRAM with ECC, 128 K x 8, -40 to 85 degC, 32-Pin SOJ (SOJ-32_B), Pb-Free; Manufacturer: Integrated Silicon Solution Inc (ISSI); PartNumber: IS61WV1288EEBLL-10KLI; Density: 1M; Organization: 128K x 8; Packing: Tray / Tube; Speed (ns): 10
footprint ISSI-SOJ-32_B_N (SOJ, 32-Leads, Body 21.08x10.29mm, Pitch 1.27mm, IPC Medium Density)
pins: 1 A0 (in) "Address Input", 2 A1 (in) "Address Input", 3 A2 (in) "Address Input", 4 A3 (in) "Address Input", 5 ~{CE} (in) "Chip Enable Input", 6 I/O0 (io) "Bidirectional Port", 7 I/O1 (io) "Bidirectional Port", 8 VDD (power) "Power", 9 GND (power) "Ground", 10 I/O2 (io) "Bidirectional Port", 11 I/O3 (io) "Bidirectional Port", 12 ~{WE} (in) "Write Enable Input", 13 A4 (in) "Address Input", 14 A5 (in) "Address Input", 15 A6 (in) "Address Input", 16 A7 (in) "Address Input", 17 A8 (in) "Address Input", 18 A9 (in) "Address Input", 19 A10 (in) "Address Input", 20 A11 (in) "Address Input", 21 A12 (in) "Address Input", 22 I/O4 (io) "Bidirectional Port", 23 I/O5 (io) "Bidirectional Port", 24 VDD (power) "Power", 25 GND (power) "Ground", 26 I/O6 (io) "Bidirectional Port", 27 I/O7 (io) "Bidirectional Port", 28 ~{OE} (in) "Output Enable Input", 29 A13 (in) "Address Input", 30 A14 (in) "Address Input", 31 A15 (in) "Address Input", 32 A16 (in) "Address Input"

## IS61WV1288EEBLL-10KLI-TR
designator U?
1 M High Speed Asynchronous CMOS SRAM with ECC, 128 K x 8, -40 to 85 degC, 32-Pin SOJ (SOJ-32_B), Pb-Free; Manufacturer: Integrated Silicon Solution Inc (ISSI); PartNumber: IS61WV1288EEBLL-10KLI-TR; Density: 1M; Organization: 128K x 8; Packing: Tape & Reel; Speed (ns): 10
footprint ISSI-SOJ-32_B_N (SOJ, 32-Leads, Body 21.08x10.29mm, Pitch 1.27mm, IPC Medium Density)
pins: 1 A0 (in) "Address Input", 2 A1 (in) "Address Input", 3 A2 (in) "Address Input", 4 A3 (in) "Address Input", 5 ~{CE} (in) "Chip Enable Input", 6 I/O0 (io) "Bidirectional Port", 7 I/O1 (io) "Bidirectional Port", 8 VDD (power) "Power", 9 GND (power) "Ground", 10 I/O2 (io) "Bidirectional Port", 11 I/O3 (io) "Bidirectional Port", 12 ~{WE} (in) "Write Enable Input", 13 A4 (in) "Address Input", 14 A5 (in) "Address Input", 15 A6 (in) "Address Input", 16 A7 (in) "Address Input", 17 A8 (in) "Address Input", 18 A9 (in) "Address Input", 19 A10 (in) "Address Input", 20 A11 (in) "Address Input", 21 A12 (in) "Address Input", 22 I/O4 (io) "Bidirectional Port", 23 I/O5 (io) "Bidirectional Port", 24 VDD (power) "Power", 25 GND (power) "Ground", 26 I/O6 (io) "Bidirectional Port", 27 I/O7 (io) "Bidirectional Port", 28 ~{OE} (in) "Output Enable Input", 29 A13 (in) "Address Input", 30 A14 (in) "Address Input", 31 A15 (in) "Address Input", 32 A16 (in) "Address Input"

## IS61WV1288EEBLL-10TI
designator U?
1 M High Speed Asynchronous CMOS SRAM with ECC, 128 K x 8, -40 to 85 degC, 32-Pin SOP (TSOP-2-32); Manufacturer: Integrated Silicon Solution Inc (ISSI); PartNumber: IS61WV1288EEBLL-10TI; Density: 1M; Organization: 128K x 8; Packing: Tray / Tube; Speed (ns): 10
footprint ISSI-TSOP-2-32_N (SOP, 32-Leads, Body 21.1x10.3mm, Pitch 1.27mm, IPC Medium Density)
pins: 1 A0 (in) "Address Input", 2 A1 (in) "Address Input", 3 A2 (in) "Address Input", 4 A3 (in) "Address Input", 5 ~{CE} (in) "Chip Enable Input", 6 I/O0 (io) "Bidirectional Port", 7 I/O1 (io) "Bidirectional Port", 8 VDD (power) "Power", 9 GND (power) "Ground", 10 I/O2 (io) "Bidirectional Port", 11 I/O3 (io) "Bidirectional Port", 12 ~{WE} (in) "Write Enable Input", 13 A4 (in) "Address Input", 14 A5 (in) "Address Input", 15 A6 (in) "Address Input", 16 A7 (in) "Address Input", 17 A8 (in) "Address Input", 18 A9 (in) "Address Input", 19 A10 (in) "Address Input", 20 A11 (in) "Address Input", 21 A12 (in) "Address Input", 22 I/O4 (io) "Bidirectional Port", 23 I/O5 (io) "Bidirectional Port", 24 VDD (power) "Power", 25 GND (power) "Ground", 26 I/O6 (io) "Bidirectional Port", 27 I/O7 (io) "Bidirectional Port", 28 ~{OE} (in) "Output Enable Input", 29 A13 (in) "Address Input", 30 A14 (in) "Address Input", 31 A15 (in) "Address Input", 32 A16 (in) "Address Input"

## IS61WV1288EEBLL-10TI-TR
designator U?
1 M High Speed Asynchronous CMOS SRAM with ECC, 128 K x 8, -40 to 85 degC, 32-Pin SOP (TSOP-2-32); Manufacturer: Integrated Silicon Solution Inc (ISSI); PartNumber: IS61WV1288EEBLL-10TI-TR; Density: 1M; Organization: 128K x 8; Packing: Tape & Reel; Speed (ns): 10
footprint ISSI-TSOP-2-32_N (SOP, 32-Leads, Body 21.1x10.3mm, Pitch 1.27mm, IPC Medium Density)
pins: 1 A0 (in) "Address Input", 2 A1 (in) "Address Input", 3 A2 (in) "Address Input", 4 A3 (in) "Address Input", 5 ~{CE} (in) "Chip Enable Input", 6 I/O0 (io) "Bidirectional Port", 7 I/O1 (io) "Bidirectional Port", 8 VDD (power) "Power", 9 GND (power) "Ground", 10 I/O2 (io) "Bidirectional Port", 11 I/O3 (io) "Bidirectional Port", 12 ~{WE} (in) "Write Enable Input", 13 A4 (in) "Address Input", 14 A5 (in) "Address Input", 15 A6 (in) "Address Input", 16 A7 (in) "Address Input", 17 A8 (in) "Address Input", 18 A9 (in) "Address Input", 19 A10 (in) "Address Input", 20 A11 (in) "Address Input", 21 A12 (in) "Address Input", 22 I/O4 (io) "Bidirectional Port", 23 I/O5 (io) "Bidirectional Port", 24 VDD (power) "Power", 25 GND (power) "Ground", 26 I/O6 (io) "Bidirectional Port", 27 I/O7 (io) "Bidirectional Port", 28 ~{OE} (in) "Output Enable Input", 29 A13 (in) "Address Input", 30 A14 (in) "Address Input", 31 A15 (in) "Address Input", 32 A16 (in) "Address Input"

## IS61WV1288EEBLL-10TLI
designator U?
1 M High Speed Asynchronous CMOS SRAM with ECC, 128 K x 8, -40 to 85 degC, 32-Pin SOP (TSOP-2-32), Pb-Free; Manufacturer: Integrated Silicon Solution Inc (ISSI); PartNumber: IS61WV1288EEBLL-10TLI; Density: 1M; Organization: 128K x 8; Packing: Tray / Tube; Speed (ns): 10
footprint ISSI-TSOP-2-32_N (SOP, 32-Leads, Body 21.1x10.3mm, Pitch 1.27mm, IPC Medium Density)
pins: 1 A0 (in) "Address Input", 2 A1 (in) "Address Input", 3 A2 (in) "Address Input", 4 A3 (in) "Address Input", 5 ~{CE} (in) "Chip Enable Input", 6 I/O0 (io) "Bidirectional Port", 7 I/O1 (io) "Bidirectional Port", 8 VDD (power) "Power", 9 GND (power) "Ground", 10 I/O2 (io) "Bidirectional Port", 11 I/O3 (io) "Bidirectional Port", 12 ~{WE} (in) "Write Enable Input", 13 A4 (in) "Address Input", 14 A5 (in) "Address Input", 15 A6 (in) "Address Input", 16 A7 (in) "Address Input", 17 A8 (in) "Address Input", 18 A9 (in) "Address Input", 19 A10 (in) "Address Input", 20 A11 (in) "Address Input", 21 A12 (in) "Address Input", 22 I/O4 (io) "Bidirectional Port", 23 I/O5 (io) "Bidirectional Port", 24 VDD (power) "Power", 25 GND (power) "Ground", 26 I/O6 (io) "Bidirectional Port", 27 I/O7 (io) "Bidirectional Port", 28 ~{OE} (in) "Output Enable Input", 29 A13 (in) "Address Input", 30 A14 (in) "Address Input", 31 A15 (in) "Address Input", 32 A16 (in) "Address Input"

## IS61WV1288EEBLL-10TLI-TR
designator U?
1 M High Speed Asynchronous CMOS SRAM with ECC, 128 K x 8, -40 to 85 degC, 32-Pin SOP (TSOP-2-32), Pb-Free; Manufacturer: Integrated Silicon Solution Inc (ISSI); PartNumber: IS61WV1288EEBLL-10TLI-TR; Density: 1M; Organization: 128K x 8; Packing: Tape & Reel; Speed (ns): 10
footprint ISSI-TSOP-2-32_N (SOP, 32-Leads, Body 21.1x10.3mm, Pitch 1.27mm, IPC Medium Density)
pins: 1 A0 (in) "Address Input", 2 A1 (in) "Address Input", 3 A2 (in) "Address Input", 4 A3 (in) "Address Input", 5 ~{CE} (in) "Chip Enable Input", 6 I/O0 (io) "Bidirectional Port", 7 I/O1 (io) "Bidirectional Port", 8 VDD (power) "Power", 9 GND (power) "Ground", 10 I/O2 (io) "Bidirectional Port", 11 I/O3 (io) "Bidirectional Port", 12 ~{WE} (in) "Write Enable Input", 13 A4 (in) "Address Input", 14 A5 (in) "Address Input", 15 A6 (in) "Address Input", 16 A7 (in) "Address Input", 17 A8 (in) "Address Input", 18 A9 (in) "Address Input", 19 A10 (in) "Address Input", 20 A11 (in) "Address Input", 21 A12 (in) "Address Input", 22 I/O4 (io) "Bidirectional Port", 23 I/O5 (io) "Bidirectional Port", 24 VDD (power) "Power", 25 GND (power) "Ground", 26 I/O6 (io) "Bidirectional Port", 27 I/O7 (io) "Bidirectional Port", 28 ~{OE} (in) "Output Enable Input", 29 A13 (in) "Address Input", 30 A14 (in) "Address Input", 31 A15 (in) "Address Input", 32 A16 (in) "Address Input"

## IS61WV2568EDBLL-8BLI
designator U?
2 M High Speed Asynchronous CMOS SRAM with ECC, 256 K x 8, -40 to 85 degC, 36-Pin BGA (TF-BGA-36), Pb-Free; Manufacturer: Integrated Silicon Solution Inc (ISSI); PartNumber: IS61WV2568EDBLL-8BLI; Density: 2M; Organization: 256K x 8; Packing: Tray / Tube; Speed (ns): 8
footprint ISSI-TF-BGA-36-6000x8000DE (BGA, 36-Balls, Body 8x6mm, Pitch 0.75mm)
pins: A1 A0 (in) "Address Input", A2 A1 (in) "Address Input", A3 NC "No Connection", A4 A3 (in) "Address Input", A5 A6 (in) "Address Input", A6 A8 (in) "Address Input", B1 I/O4 (io) "Bidirectional Port", B2 A2 (in) "Address Input", B3 ~{WE} (in) "Write Enable Input", B4 A4 (in) "Address Input", B5 A7 (in) "Address Input", B6 I/O0 (io) "Bidirectional Port", C1 I/O5 (io) "Bidirectional Port", C3 NC "No Connection", C4 A5 (in) "Address Input", C6 I/O1 (io) "Bidirectional Port", D1 GND (power) "Ground", D6 VDD (power) "Power", E1 VDD (power) "Power", E6 GND (power) "Ground", F1 I/O6 (io) "Bidirectional Port", F3 NC "No Connection", F4 A17 (in) "Address Input", F6 I/O2 (io) "Bidirectional Port", G1 I/O7 (io) "Bidirectional Port", G2 ~{OE} (in) "Output Enable Input", G3 ~{CE} (in) "Chip Enable Input", G4 A16 (in) "Address Input", G5 A15 (in) "Address Input", G6 I/O3 (io) "Bidirectional Port", H1 A9 (in) "Address Input", H2 A10 (in) "Address Input", H3 A11 (in) "Address Input", H4 A12 (in) "Address Input", H5 A13 (in) "Address Input", H6 A14 (in) "Address Input"

## IS61WV2568EDBLL-8BLI-TR
designator U?
2 M High Speed Asynchronous CMOS SRAM with ECC, 256 K x 8, -40 to 85 degC, 36-Pin BGA (TF-BGA-36), Pb-Free; Manufacturer: Integrated Silicon Solution Inc (ISSI); PartNumber: IS61WV2568EDBLL-8BLI-TR; Density: 2M; Organization: 256K x 8; Packing: Tape & Reel; Speed (ns): 8
footprint ISSI-TF-BGA-36-6000x8000DE (BGA, 36-Balls, Body 8x6mm, Pitch 0.75mm)
pins: A1 A0 (in) "Address Input", A2 A1 (in) "Address Input", A3 NC "No Connection", A4 A3 (in) "Address Input", A5 A6 (in) "Address Input", A6 A8 (in) "Address Input", B1 I/O4 (io) "Bidirectional Port", B2 A2 (in) "Address Input", B3 ~{WE} (in) "Write Enable Input", B4 A4 (in) "Address Input", B5 A7 (in) "Address Input", B6 I/O0 (io) "Bidirectional Port", C1 I/O5 (io) "Bidirectional Port", C3 NC "No Connection", C4 A5 (in) "Address Input", C6 I/O1 (io) "Bidirectional Port", D1 GND (power) "Ground", D6 VDD (power) "Power", E1 VDD (power) "Power", E6 GND (power) "Ground", F1 I/O6 (io) "Bidirectional Port", F3 NC "No Connection", F4 A17 (in) "Address Input", F6 I/O2 (io) "Bidirectional Port", G1 I/O7 (io) "Bidirectional Port", G2 ~{OE} (in) "Output Enable Input", G3 ~{CE} (in) "Chip Enable Input", G4 A16 (in) "Address Input", G5 A15 (in) "Address Input", G6 I/O3 (io) "Bidirectional Port", H1 A9 (in) "Address Input", H2 A10 (in) "Address Input", H3 A11 (in) "Address Input", H4 A12 (in) "Address Input", H5 A13 (in) "Address Input", H6 A14 (in) "Address Input"

## IS61WV2568EDBLL-8KLI
designator U?
2 M High Speed Asynchronous CMOS SRAM with ECC, 256 K x 8, -40 to 85 degC, 36-Pin SOJ (SOJ-36), Pb-Free; Manufacturer: Integrated Silicon Solution Inc (ISSI); PartNumber: IS61WV2568EDBLL-8KLI; Density: 2M; Organization: 256K x 8; Packing: Tray / Tube; Speed (ns): 8
footprint ISSI-SOJ-36_N (SOJ, 36-Leads, Body 23.62x10.29mm, Pitch 1.27mm, IPC Medium Density)
pins: 1 A0 (in) "Address Input", 2 A1 (in) "Address Input", 3 A2 (in) "Address Input", 4 A3 (in) "Address Input", 5 A4 (in) "Address Input", 6 ~{CE} (in) "Chip Enable Input", 7 I/O0 (io) "Bidirectional Port", 8 I/O1 (io) "Bidirectional Port", 9 VDD (power) "Power", 10 GND (power) "Ground", 11 I/O2 (io) "Bidirectional Port", 12 I/O3 (io) "Bidirectional Port", 13 ~{WE} (in) "Write Enable Input", 14 A5 (in) "Address Input", 15 A6 (in) "Address Input", 16 A7 (in) "Address Input", 17 A8 (in) "Address Input", 18 A9 (in) "Address Input", 19 NC "No Connection", 20 NC "No Connection", 21 A10 (in) "Address Input", 22 A11 (in) "Address Input", 23 A12 (in) "Address Input", 24 A13 (in) "Address Input", 25 I/O4 (io) "Bidirectional Port", 26 I/O5 (io) "Bidirectional Port", 27 VDD (power) "Power", 28 GND (power) "Ground", 29 I/O6 (io) "Bidirectional Port", 30 I/O7 (io) "Bidirectional Port", 31 ~{OE} (in) "Output Enable Input", 32 A14 (in) "Address Input", 33 A15 (in) "Address Input", 34 A16 (in) "Address Input", 35 A17 (in) "Address Input", 36 NC "No Connection"

## IS61WV2568EDBLL-8KLI-TR
designator U?
2 M High Speed Asynchronous CMOS SRAM with ECC, 256 K x 8, -40 to 85 degC, 36-Pin SOJ (SOJ-36), Pb-Free; Manufacturer: Integrated Silicon Solution Inc (ISSI); PartNumber: IS61WV2568EDBLL-8KLI-TR; Density: 2M; Organization: 256K x 8; Packing: Tape & Reel; Speed (ns): 8
footprint ISSI-SOJ-36_N (SOJ, 36-Leads, Body 23.62x10.29mm, Pitch 1.27mm, IPC Medium Density)
pins: 1 A0 (in) "Address Input", 2 A1 (in) "Address Input", 3 A2 (in) "Address Input", 4 A3 (in) "Address Input", 5 A4 (in) "Address Input", 6 ~{CE} (in) "Chip Enable Input", 7 I/O0 (io) "Bidirectional Port", 8 I/O1 (io) "Bidirectional Port", 9 VDD (power) "Power", 10 GND (power) "Ground", 11 I/O2 (io) "Bidirectional Port", 12 I/O3 (io) "Bidirectional Port", 13 ~{WE} (in) "Write Enable Input", 14 A5 (in) "Address Input", 15 A6 (in) "Address Input", 16 A7 (in) "Address Input", 17 A8 (in) "Address Input", 18 A9 (in) "Address Input", 19 NC "No Connection", 20 NC "No Connection", 21 A10 (in) "Address Input", 22 A11 (in) "Address Input", 23 A12 (in) "Address Input", 24 A13 (in) "Address Input", 25 I/O4 (io) "Bidirectional Port", 26 I/O5 (io) "Bidirectional Port", 27 VDD (power) "Power", 28 GND (power) "Ground", 29 I/O6 (io) "Bidirectional Port", 30 I/O7 (io) "Bidirectional Port", 31 ~{OE} (in) "Output Enable Input", 32 A14 (in) "Address Input", 33 A15 (in) "Address Input", 34 A16 (in) "Address Input", 35 A17 (in) "Address Input", 36 NC "No Connection"

## IS61WV2568EDBLL-8TLI
designator U?
2 M High Speed Asynchronous CMOS SRAM with ECC, 256 K x 8, -40 to 85 degC, 44-Pin SOP (TSOP-2-44), Pb-Free; Manufacturer: Integrated Silicon Solution Inc (ISSI); PartNumber: IS61WV2568EDBLL-8TLI; Density: 2M; Organization: 256K x 8; Packing: Tray / Tube; Speed (ns): 8
footprint ISSI-TSOP-2-44_N (SOP, 44-Leads, Body 18.5x10.3mm, Pitch 0.8mm, IPC Medium Density)
part A pins: 3 A0 (in) "Address Input", 4 A1 (in) "Address Input", 5 A2 (in) "Address Input", 6 A3 (in) "Address Input", 7 A4 (in) "Address Input", 8 ~{CE} (in) "Chip Enable Input", 9 I/O0 (io) "Bidirectional Port", 10 I/O1 (io) "Bidirectional Port", 11 VDD (power) "Power", 12 GND (power) "Ground", 13 I/O2 (io) "Bidirectional Port", 14 I/O3 (io) "Bidirectional Port", 15 ~{WE} (in) "Write Enable Input", 16 A5 (in) "Address Input", 17 A6 (in) "Address Input", 18 A7 (in) "Address Input", 19 A8 (in) "Address Input", 20 A9 (in) "Address Input", 27 A10 (in) "Address Input", 28 A11 (in) "Address Input", 29 A12 (in) "Address Input", 30 A13 (in) "Address Input", 31 I/O4 (io) "Bidirectional Port", 32 I/O5 (io) "Bidirectional Port", 33 VDD (power) "Power", 34 GND (power) "Ground", 35 I/O6 (io) "Bidirectional Port", 36 I/O7 (io) "Bidirectional Port", 37 ~{OE} (in) "Output Enable Input", 38 A14 (in) "Address Input", 39 A15 (in) "Address Input", 40 A16 (in) "Address Input", 41 A17 (in) "Address Input"
part B pins: 1 NC "No Connection", 2 NC "No Connection", 21 NC "No Connection", 22 NC "No Connection", 23 NC "No Connection", 24 NC "No Connection", 25 NC "No Connection", 26 NC "No Connection", 42 NC "No Connection", 43 NC "No Connection", 44 NC "No Connection"

## IS61WV2568EDBLL-8TLI-TR
designator U?
2 M High Speed Asynchronous CMOS SRAM with ECC, 256 K x 8, -40 to 85 degC, 44-Pin SOP (TSOP-2-44), Pb-Free; Manufacturer: Integrated Silicon Solution Inc (ISSI); PartNumber: IS61WV2568EDBLL-8TLI-TR; Density: 2M; Organization: 256K x 8; Packing: Tape & Reel; Speed (ns): 8
footprint ISSI-TSOP-2-44_N (SOP, 44-Leads, Body 18.5x10.3mm, Pitch 0.8mm, IPC Medium Density)
part A pins: 3 A0 (in) "Address Input", 4 A1 (in) "Address Input", 5 A2 (in) "Address Input", 6 A3 (in) "Address Input", 7 A4 (in) "Address Input", 8 ~{CE} (in) "Chip Enable Input", 9 I/O0 (io) "Bidirectional Port", 10 I/O1 (io) "Bidirectional Port", 11 VDD (power) "Power", 12 GND (power) "Ground", 13 I/O2 (io) "Bidirectional Port", 14 I/O3 (io) "Bidirectional Port", 15 ~{WE} (in) "Write Enable Input", 16 A5 (in) "Address Input", 17 A6 (in) "Address Input", 18 A7 (in) "Address Input", 19 A8 (in) "Address Input", 20 A9 (in) "Address Input", 27 A10 (in) "Address Input", 28 A11 (in) "Address Input", 29 A12 (in) "Address Input", 30 A13 (in) "Address Input", 31 I/O4 (io) "Bidirectional Port", 32 I/O5 (io) "Bidirectional Port", 33 VDD (power) "Power", 34 GND (power) "Ground", 35 I/O6 (io) "Bidirectional Port", 36 I/O7 (io) "Bidirectional Port", 37 ~{OE} (in) "Output Enable Input", 38 A14 (in) "Address Input", 39 A15 (in) "Address Input", 40 A16 (in) "Address Input", 41 A17 (in) "Address Input"
part B pins: 1 NC "No Connection", 2 NC "No Connection", 21 NC "No Connection", 22 NC "No Connection", 23 NC "No Connection", 24 NC "No Connection", 25 NC "No Connection", 26 NC "No Connection", 42 NC "No Connection", 43 NC "No Connection", 44 NC "No Connection"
